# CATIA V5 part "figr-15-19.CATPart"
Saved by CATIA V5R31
Part number: Part1
Bounding box of the stored display mesh (mm): x -46.56 to 46.56, y -36.965 to 25.965, z 0 to 40
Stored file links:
  D:\PROJECTS\Project 2021\US EDITION\CATIA V5 6R 2021\Resources\Part Files\c15_catia_v5_6r2021_prt\figr-15-19.CATPart
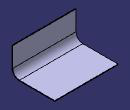
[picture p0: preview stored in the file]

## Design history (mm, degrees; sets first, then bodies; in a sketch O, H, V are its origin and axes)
SheetMetalParameters1: Thickness 1, BendRadius 1, KFactor 0.325257 {= log(min(100,max(20*SheetMetalParameters1.BendRadius,SheetMetalParameters1.Thickness)/SheetMetalParameters1.Thickness))/log(100)/2}, ReliefRadialLength 1, ReliefAxialLength 2, MinimumBendRadius 0
Body1 (main body)
  Sketch1 on xy-plane, origin (0, 0, 0), H (1, 0, 0), V (0, 1, 0)
    line L1 (-46.5596, 25.9646) -> (46.5596, 25.9646)
    line L2 (46.5596, 25.9646) -> (46.5596, -25.9646)
    line L3 (46.5596, -25.9646) -> (-46.5596, -25.9646)
    line L4 (-46.5596, -25.9646) -> (-46.5596, 25.9646)
    horizontal: L1 H, L3 H
    vertical: L2 V, L4 V
    symmetry: L1 L3 H, L4 L2 V
  Wall1: Thickness 1, Profile Sketch1
  d_NewWallOnEdge1: NewWallOnEdge_Edge edge [face of Wall1 | face of Wall1], NewWallOnEdge_Length 40, NewWallOnEdge_HeightLimitOffset 0, NewWallOnEdge_WidthOffset1 0, NewWallOnEdge_WidthOffset2 0, NewWallOnEdge_Angle 90, NewWallOnEdge_BendRadiusValue 10 {= d_NewWallOnEdge1.Clearance}, NewWallOnEdge_BendTable SheetMetalParameters1, KFacteur 0.5 {= log(min(100,max(20*d_NewWallOnEdge1.Radius,SheetMetalParameters1.Thickness)/SheetMetalParameters1.Thickness))/log(100)/2}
